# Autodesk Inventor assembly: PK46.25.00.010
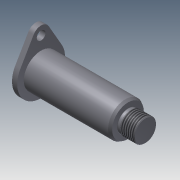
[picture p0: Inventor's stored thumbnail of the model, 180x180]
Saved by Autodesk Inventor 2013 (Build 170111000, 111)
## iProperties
Created: 2005-05
Part Number: PK46.25.00.010
Document SubType Name: Assembly
Designer: PVitaliy
Manufacturer: Standard
Standards Organization: Custom
Author: PVitaliy
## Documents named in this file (3)
- D:\FrontLoaderVault\Data\Assy, Chassis, Front\PK46.25.00.010.iam
- D:\FrontLoaderVault\Data\Assy, Chassis, Front\PK46.25.00.001.ipt
- D:\FrontLoaderVault\Data\Assy, Chassis, Front\PK46.25.00.002.ipt
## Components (2 placed, 2 different names)
1. PK46.25.00.001:1 — Insert:1
2. PK46.25.00.002:1 — Insert:1, Mate:1
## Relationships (2: Insert 1, Mate 1)
- Insert:1: PK46.25.00.001:1 ↔ PK46.25.00.002:1
- Mate:1: PK46.25.00.002:1
